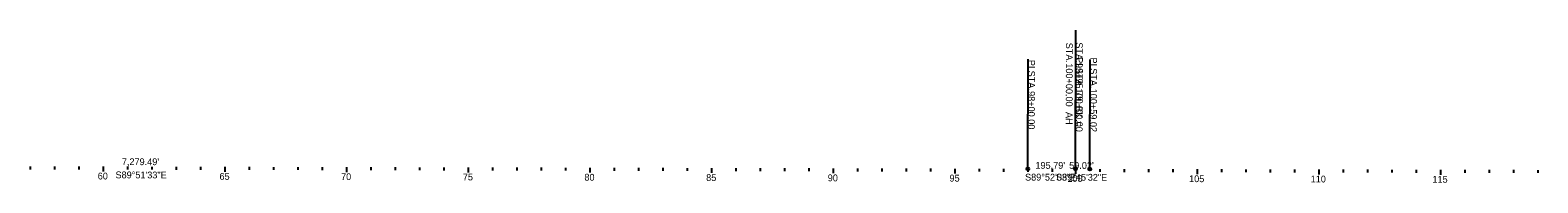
# Model space of a CAD drawing. Extents: x 117326 to 225548, y 573011 to 581051.
# Drawn here: x 123537 to 129733, y 574969 to 575596 of the extents above; entities that cross this region are included whole.
import ezdxf

# ---------------------------------------------------------------- set-up
doc = ezdxf.new("R2010")
doc.units = 0
for name, color, linetype in [('_CIVIL_CONSTRUCTION', 7, 'Continuous'), ('GE_P_Alignment', 7, 'Continuous'), ('GE_P_Alignment_100_Cardinal_Points', 7, 'Continuous'), ('GE_P_Alignment_100_Curve_Data', 7, 'Continuous')]:
    doc.layers.add(name, color=color, linetype=linetype)

msp = doc.modelspace()

# ---------------------------------------------------------------- linework, layer by layer
at = {"layer": 'GE_P_Alignment'}
for p, q in [((127833, 575026), (127834.3, 575596)), ((127637.2, 575026.5), (127638.2, 575476.5)), ((127833, 575026), (127834.9, 575476)), ((127892, 575025.8), (127893, 575475.8))]:
    msp.add_line(p, q, dxfattribs=at)
for centre in [(127637.2, 575026.5), (127833, 575026), (127833, 575026), (127892, 575025.8)]:
    msp.add_circle(centre, 6, dxfattribs=at)
at = {"layer": 'GE_P_Alignment_100_Curve_Data'}
for p, q in [((123537.2, 575036.5), (123537.2, 575024.5)), ((123637.2, 575036.3), (123637.2, 575024.3)), ((123737.2, 575036.1), (123737.2, 575024.1)), ((123837.2, 575035.8), (123837.1, 575015.8)), ((123937.2, 575035.6), (123937.2, 575023.6)), ((124037.2, 575035.3), (124037.2, 575023.3)), ((124137.2, 575035.1), (124137.2, 575023.1)), ((124237.2, 575034.8), (124237.2, 575022.8)), ((124337.2, 575034.6), (124337.1, 575014.6)), ((124437.2, 575034.3), (124437.2, 575022.3)), ((124537.2, 575034.1), (124537.2, 575022.1)), ((124637.2, 575033.8), (124637.2, 575021.8)), ((124737.2, 575033.6), (124737.2, 575021.6)), ((124837.2, 575033.4), (124837.1, 575013.4)), ((124937.2, 575033.1), (124937.2, 575021.1)), ((125037.2, 575032.9), (125037.2, 575020.9)), ((125137.2, 575032.6), (125137.2, 575020.6)), ((125237.2, 575032.4), (125237.2, 575020.4)), ((125337.2, 575032.1), (125337.1, 575012.1)), ((125437.2, 575031.9), (125437.2, 575019.9)), ((125537.2, 575031.6), (125537.2, 575019.6)), ((125637.2, 575031.4), (125637.2, 575019.4)), ((125737.2, 575031.1), (125737.2, 575019.1)), ((125837.2, 575030.9), (125837.1, 575010.9)), ((125937.2, 575030.7), (125937.2, 575018.7)), ((126037.2, 575030.4), (126037.2, 575018.4)), ((126137.2, 575030.2), (126137.2, 575018.2)), ((126237.2, 575029.9), (126237.2, 575017.9)), ((126337.2, 575029.7), (126337.1, 575009.7)), ((126437.2, 575029.4), (126437.2, 575017.4)), ((126537.2, 575029.2), (126537.2, 575017.2)), ((126637.2, 575028.9), (126637.2, 575016.9)), ((126737.2, 575028.7), (126737.2, 575016.7)), ((126837.2, 575028.4), (126837.1, 575008.4)), ((126937.2, 575028.2), (126937.1, 575016.2)), ((127037.2, 575028), (127037.1, 575016)), ((127137.2, 575027.7), (127137.1, 575015.7)), ((127237.2, 575027.5), (127237.1, 575015.5)), ((127337.2, 575027.2), (127337.1, 575007.2)), ((127437.2, 575027), (127437.1, 575015)), ((127537.2, 575026.7), (127537.1, 575014.7)), ((127637.2, 575026.5), (127637.1, 575014.5)), ((127737.2, 575026.3), (127737.1, 575014.3)), ((127833, 575026), (127832.9, 575006)), ((127933, 575025.7), (127932.9, 575013.7)), ((128033, 575025.5), (128032.9, 575013.5)), ((128133, 575025.2), (128132.9, 575013.2)), ((128233, 575025), (128232.9, 575013)), ((128333, 575024.8), (128332.9, 575004.8)), ((128433, 575024.6), (128432.9, 575012.6)), ((128533, 575024.3), (128532.9, 575012.3)), ((128633, 575024.1), (128632.9, 575012.1)), ((128733, 575023.9), (128732.9, 575011.9)), ((128833, 575023.7), (128832.9, 575003.7)), ((128933, 575023.4), (128932.9, 575011.4)), ((129033, 575023.2), (129032.9, 575011.2)), ((129133, 575023), (129132.9, 575011)), ((129233, 575022.8), (129232.9, 575010.8)), ((129333, 575022.6), (129332.9, 575002.6)), ((129433, 575022.3), (129432.9, 575010.3)), ((129533, 575022.1), (129532.9, 575010.1)), ((129633, 575021.9), (129632.9, 575009.9)), ((129733, 575021.7), (129732.9, 575009.7))]:
    msp.add_line(p, q, dxfattribs=at)

# ---------------------------------------------------------------- texts
at = {"layer": '_CIVIL_CONSTRUCTION'}
for s, rotation, p in [('S89°51\'33"E', 359.85931, (123887.9, 574987.7)), ('S89°52\'03"E', 359.86751, (127625.6, 574978.5)), ('S89°45\'32"E', 359.75882, (127752.9, 574978.4))]:
    msp.add_text(s, height=28, rotation=rotation, dxfattribs=at).set_placement(p)
at = {"layer": 'GE_P_Alignment'}
for s, rotation, p in [('STA. ', 269.86751, (127793.7, 575544.6)), ('STA. ', 269.86751, (127834.6, 575546)), ('PI', 269.86751, (127638.6, 575474.2)), ('PI', 269.75882, (127835.3, 575485)), ('PI', 269.87155, (127893.4, 575484.1)), (' STA. ', 269.86751, (127638.6, 575440.3)), ('100+00.00', 269.86751, (127793.5, 575460)), ('99+95.79', 269.86751, (127834.4, 575461.4)), (' STA. ', 269.75882, (127835.2, 575451.1)), (' STA. ', 269.87155, (127893.4, 575450.1)), ('98+00.00', 269.86751, (127638.3, 575345.8)), ('100+00.00', 269.75882, (127834.8, 575356.5)), ('100+59.02', 269.87155, (127893.1, 575355.6)), (' BK =', 269.86751, (127834, 575294.2)), (' AH', 269.86751, (127793, 575270.4))]:
    msp.add_text(s, height=28, rotation=rotation, dxfattribs=at).set_placement(p)
at = {"layer": 'GE_P_Alignment_100_Cardinal_Points'}
for s, rotation, p in [("7,279.49'", 359.85931, (123914, 575041.9)), ("195.79'", 359.86751, (127668.3, 575026.8)), ("59.02'", 359.75882, (127806.9, 575026.6))]:
    msp.add_text(s, height=28, rotation=rotation, dxfattribs=at).set_placement(p)
at = {"layer": 'GE_P_Alignment_100_Curve_Data'}
for s, rotation, p in [('60', 359.85931, (123814.8, 574982.9)), ('65', 359.85931, (124315.2, 574981.6)), ('70', 359.85931, (124814.8, 574980.4)), ('75', 359.85931, (125315.2, 574979.2)), ('80', 359.85931, (125814.8, 574978)), ('85', 359.85931, (126315.2, 574976.7)), ('90', 359.85931, (126814.8, 574975.5)), ('95', 359.85931, (127315.2, 574974.3)), ('100', 359.86751, (127799.4, 574973.1)), ('105', 359.87155, (128299.8, 574971.9)), ('110', 359.87155, (128799.4, 574970.7)), ('115', 359.87155, (129299.8, 574969.6))]:
    msp.add_text(s, height=28, rotation=rotation, dxfattribs=at).set_placement(p)

doc.saveas('drawing.dxf')
